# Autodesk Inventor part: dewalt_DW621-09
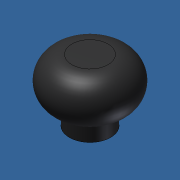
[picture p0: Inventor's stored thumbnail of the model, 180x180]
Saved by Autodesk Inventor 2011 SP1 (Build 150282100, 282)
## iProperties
Created: 2011-02
Part Number: dewalt_DW621-09
Material: Gummi
Catalog Web Link: www.mittelmeyer.de
Document SubType Name: Modellieren
Designer: TMT
Manufacturer: Standard
Standards Organization: Custom
Density: 0.93 g/cm^3
Author: TMT
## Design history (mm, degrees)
sketch "Skizze2"
  geometry: C1 r 31.5 at (0, 0); 1 further point
  constraints: 1 centre point, 1 coincident
  dimensions: "d5" = 63 diameter of C1 (= durchmesser_01)
extrude "Extrusion2" new body sketch "Skizze2" distance "d6" = 35 (= hoehe_01); taper "d7" = 0 deg
fillet "Rundung3" dims "d8" = 17.5
sketch "Skizze3"
  geometry: C1 r 14 at (0, 0) reference; C2 r 16 at (0, 0)
  constraints: 1 centre point, 1 coincident
  dimensions: "d9" = 32 diameter of C2
extrude "Extrusion3" join sketch "Skizze3" distance "d10" = 13; taper "d11" = 0 deg
node "Volumenkörper1"
node "Volumenkörpern"
node "Oberflächenkörpern"
other parameters: "durchmesser_01" = 63 [user parameter; used in 1 equation term], "hoehe_01" = 35 [user parameter; used in 1 equation term]
